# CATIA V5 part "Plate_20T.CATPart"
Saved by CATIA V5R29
Part number: Plate_20T
Bounding box of the stored display mesh (mm): x 0 to 120, y -250 to 250, z -60 to 60
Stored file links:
  C:\Users\Administrator\Desktop\프로젝트\Boxfold\Plate_20T.CATPart
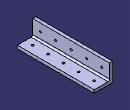
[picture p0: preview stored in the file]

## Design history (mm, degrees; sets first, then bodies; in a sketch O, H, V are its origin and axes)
Body1 (main body)
  DatumCurve1 to DatumCurve3
  Sketch1 on yz-plane, origin (0, 0, 0), H (0, 1, 0), V (0, 0, 1)
    line L1 (250, 60) -> (250, -60)
    line L2 (250, -60) -> (-250, -60)
    line L3 (-250, -60) -> (-250, 60)
    line L4 (-250, 60) -> (250, 60)
    distance L1 L3 = 500
    distance L2 L4 = 120
    vertical: L1 V, L3 V
    horizontal: L2 H, L4 H
    equidistance: L1 L3 O, L2 L4 O
  Pad1: profile Sketch1, direction (1, 0, 0), length 20
  Sketch2 on end face of Pad1, origin (20, 0, 0), H (0, 1, 0), V (0, 0, 1)
    point P1 (0, -50)
    line L1 (250, -40) -> (250, -60)
    line L2 (250, -60) -> (-250, -60)
    line L3 (-250, -60) -> (-250, -40)
    line L4 (-250, -40) -> (250, -40)
    reference projected line E1 (-250, 60) -> (-250, -60) from edge [face of Pad1 from Sketch1.L3 | end face of Pad1]
    reference projected line E2 (-250, -60) -> (250, -60) from edge [face of Pad1 from Sketch1.L2 | end face of Pad1]
    distance L4 L2 = 20
    coincidence: P1 V, L3 E1, L2 E2
    vertical: L1 V, L3 V
    horizontal: L2 H, L4 H
    equidistance: L1 L3 P1, L2 L4 P1
  Pad2: profile Sketch2, direction (1, 0, 0), length 100
  Fillet1: radius 10, on edge [end face of Pad1 | face of Pad2 from Sketch2.L4]
  Fillet2: radius 10, on edge [start face of Pad1 | face of Pad2]
  Sketch3 on face of Pad2 from Sketch2.L4, origin (79.6095, 183.5891, -40), H (1, 0, 0), V (0, 1, 0)
    point P1 (-9.6095, 16.4109)
    reference projected line E1 (40.3905, 66.4109) -> (40.3905, -433.5891) from edge [face of Pad2 from Sketch2.L4 | end face of Pad2]
    reference projected line E2 (-59.6095, 66.4109) -> (40.3905, 66.4109) from edge [face of Pad2 from Sketch2.L4 | face of Pad2]
    distance P1 E1 = 50
    distance E2 P1 = 50
  Hole1: placed by Sketch3, at (70, 200, -40) direction (0, 0, -1), diameter 8.6, through (limit type 6), counterbore diameter 14, counterbore depth 8.6
  RectPattern1: of Hole1, direction 1 instances 5, spacing 100, along edge [face of Pad2 from Sketch2.L4 | end face of Pad2]
  Sketch4 on end face of Pad1, origin (20, 210.3136, 16.2879), H (0, 1, 0), V (0, 0, 1)
    point P1 (-10.3136, -6.2879)
    reference projected line E1 (39.6864, 43.7121) -> (-460.3136, 43.7121) from edge [face of Pad1 from Sketch1.L4 | end face of Pad1]
    reference projected line E2 (39.6864, -76.2879) -> (39.6864, 43.7121) from edge [face of Pad2 | end face of Pad1]
    distance P1 E1 = 50
    distance E2 P1 = 50
  Hole2: placed by Sketch4, at (20, 200, 10) direction (-1, 0, 0), diameter 8.6, through (limit type 6), counterbore diameter 14, counterbore depth 8.6
  RectPattern2: of Hole2, direction 1 instances 5, spacing 100, along edge [face of Pad1 from Sketch1.L4 | end face of Pad1]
